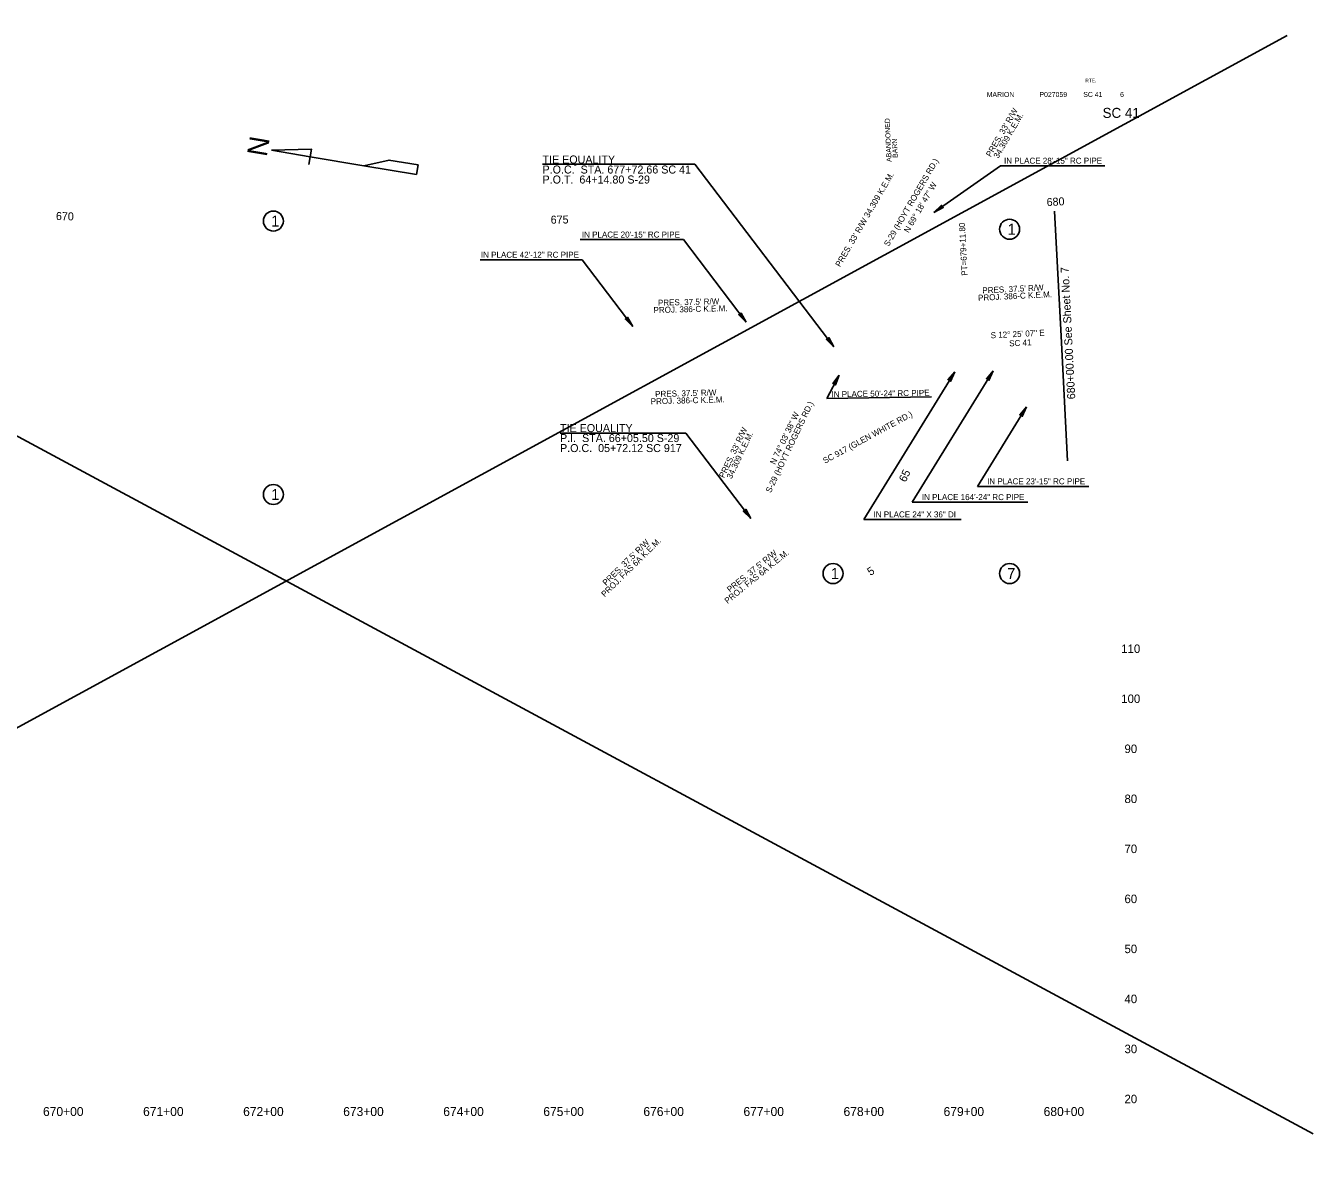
# Model space of a CAD drawing. Extents: x 2522404 to 2525275, y 885432 to 893540.
# Drawn here: x 2523877 to 2525164, y 886638 to 887766 of the extents above; entities that cross this region are included whole.
import ezdxf

# ---------------------------------------------------------------- set-up
doc = ezdxf.new("R2010")
doc.units = 0
for name, color, linetype in [('Default', 7, 'Continuous'), ('GN_Clip', 7, 'Continuous'), ('RD_DDB_ElevTX', 7, 'Continuous'), ('RD_DDB_Profile_EX', 7, 'Continuous'), ('RD_DDB_Profile_Lbl', 7, 'Continuous'), ('RD_EX_Misc', 7, 'Continuous'), ('RD_HC_Cl', 7, 'Continuous'), ('RD_HC_Data_Tic', 7, 'Continuous'), ('RD_HC_TX_Sta50', 7, 'Continuous'), ('RD_HY_TX1', 7, 'Continuous'), ('RD_PD_Final_LnLine', 7, 'Continuous'), ('RD_PD_RW_TX', 7, 'Continuous'), ('RD_SHT_IplotShp', 7, 'Continuous'), ('RD_SHT_MatchLine', 7, 'Continuous'), ('RD_Sketch8', 7, 'Continuous')]:
    doc.layers.add(name, color=color, linetype=linetype)

# ---------------------------------------------------------------- blocks, each defined once
blk = doc.blocks.new('ah_')
at = {"layer": 'Default'}
blk.add_lwpolyline([(0, 0), (-1.4, -10.4), (0, -8.8), (1.5, -10.4)], close=True, dxfattribs=at)
blk = doc.blocks.new('ah4')
at = {"layer": 'Default', "rotation": -90.00000000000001}
blk.add_blockref('ah_', (0, 0), dxfattribs=at)
blk = doc.blocks.new('AH4_')
at = {"layer": 'Default'}
blk.add_lwpolyline([(0, 0), (-10.4, 1.5), (-8.8, 0), (-10.4, -1.5)], close=True, dxfattribs=at)

msp = doc.modelspace()

# ---------------------------------------------------------------- linework, layer by layer
at = {"layer": 'RD_DDB_ElevTX'}
for p, q in [((2523107.1, 887765.8), (2525164, 886658.3)), ((2523086.7, 886637.9), (2525137.9, 887755.9))]:
    msp.add_line(p, q, dxfattribs=at)
at = {"layer": 'RD_EX_Misc'}
for centre in [(2524124.8, 887570.6), (2524860.6, 887562.4), (2524124.8, 887297.3), (2524684.1, 887218.3), (2524860.6, 887218.3)]:
    msp.add_circle(centre, 10, dxfattribs=at)
at = {"layer": 'RD_HY_TX1'}
for p, q in [((2524785, 887579.2), (2524851.4, 887625.8)), ((2524851.4, 887625.8), (2524955.9, 887625.8)), ((2524597.4, 887469.5), (2524534.6, 887552)), ((2524484, 887465.3), (2524433.4, 887531.9)), ((2524690.2, 887416.6), (2524677.8, 887393.3)), ((2524782.6, 887395), (2524677.8, 887393.3))]:
    msp.add_line(p, q, dxfattribs=at)
for points in [[(2524534.6, 887552), (2524431.5, 887552)], [(2524433.4, 887531.9), (2524331.5, 887531.9)], [(2524805.7, 887420), (2524714.8, 887272.3)], [(2524844.1, 887421), (2524763.2, 887289.6)], [(2524877.5, 887385), (2524828.4, 887305.4)], [(2524939.9, 887305.4), (2524828.4, 887305.4)], [(2524878.7, 887289.6), (2524763.2, 887289.6)], [(2524812.2, 887272.3), (2524714.9, 887272.3)]]:
    msp.add_lwpolyline(points, dxfattribs=at)
at = {"layer": 'RD_PD_RW_TX'}
for p, q in [((2524393.8, 887627.3), (2524546.1, 887627.3)), ((2524546.1, 887627.3), (2524684.9, 887444.9)), ((2524411.3, 887358.7), (2524536.9, 887358.7)), ((2524536.9, 887358.7), (2524601.9, 887273.3))]:
    msp.add_line(p, q, dxfattribs=at)
at = {"layer": 'RD_SHT_MatchLine'}
msp.add_lwpolyline([(2524918.4, 887330.8), (2524912, 887455.6), (2524905.6, 887580.5)], dxfattribs=at)
at = {"layer": 'RD_Sketch8'}
for p, q in [((2524163, 887642.6), (2524123, 887641.3)), ((2524123, 887641.3), (2524123, 887641.3)), ((2524123, 887641.3), (2524161.7, 887634.9)), ((2524161.7, 887634.9), (2524163, 887642.6)), ((2524163, 887642.6), (2524162.5, 887642.7)), ((2524160.4, 887627.1), (2524161.7, 887634.9)), ((2524215.3, 887625.9), (2524161.7, 887634.9)), ((2524240.6, 887631.6), (2524215.3, 887625.9)), ((2524215.3, 887625.9), (2524268, 887617.1)), ((2524269.6, 887626.7), (2524240.3, 887631.6)), ((2524240.3, 887631.6), (2524240.6, 887631.6)), ((2524268, 887617.1), (2524269.6, 887626.7))]:
    msp.add_line(p, q, dxfattribs=at)

# ---------------------------------------------------------------- block references
at = {"layer": 'RD_HY_TX1'}
for p, rotation in [((2524785, 887579.2), -145.18007028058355), ((2524484, 887465.3), -52.99465340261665), ((2524597.4, 887469.5), -52.99465340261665), ((2524690.2, 887416.6), 61.635532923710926)]:
    msp.add_blockref('ah4', p, dxfattribs=dict(at, rotation=rotation))
at = {"layer": 'RD_HY_TX1', "yscale": -0.9999999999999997, "rotation": 58.65092228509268}
for p in [(2524805.7, 887420), (2524844.1, 887421), (2524877.5, 887385)]:
    msp.add_blockref('ah4', p, dxfattribs=at)
at = {"layer": 'RD_PD_Final_LnLine'}
for p, rotation in [((2524684.9, 887444.9), -52.99465340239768), ((2524601.9, 887273.3), -52.9946534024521)]:
    msp.add_blockref('AH4_', p, dxfattribs=dict(at, rotation=rotation))

# ---------------------------------------------------------------- texts
at = {"layer": 'GN_Clip'}
for s, p in [('670+00', (2523894.6, 886676.1)), ('671+00', (2523994.6, 886676.1)), ('672+00', (2524094.6, 886676.1)), ('673+00', (2524194.6, 886676.1)), ('674+00', (2524294.6, 886676.1)), ('675+00', (2524394.6, 886676.1)), ('676+00', (2524494.6, 886676.1)), ('677+00', (2524594.6, 886676.1)), ('678+00', (2524694.6, 886676.1)), ('679+00', (2524794.6, 886676.1)), ('680+00', (2524894.6, 886676.1))]:
    msp.add_text(s, height=9, dxfattribs=at).set_placement(p)
at = {"layer": 'RD_DDB_Profile_EX'}
for s, rotation, p in [('680', 2.9168, (2524897.8, 887585.5)), ('670', 358.3577, (2523907.4, 887571.7)), ('675', 0.8578, (2524402, 887567.9)), ('65', 64.5588, (2524756.7, 887309)), ('5', 32.9169, (2524721.5, 887215.8))]:
    msp.add_text(s, height=8, rotation=rotation, dxfattribs=at).set_placement(p)
at = {"layer": 'RD_DDB_Profile_Lbl'}
for s, p in [('1', (2524122.6, 887565.1)), ('1', (2524858.5, 887556.9)), ('1', (2524122.6, 887291.8)), ('1', (2524681.9, 887212.8)), ('7', (2524858.1, 887212.8))]:
    msp.add_text(s, height=11, dxfattribs=at).set_placement(p)
at = {"layer": 'RD_EX_Misc'}
for s, height, p in [('RTE.', 3.5, (2524936.3, 887709.3)), ('MARION', 5, (2524837.7, 887694.6)), ('P027059', 5, (2524890.4, 887694.6)), ('SC 41', 5, (2524934.2, 887694.6)), ('6', 5, (2524971, 887694.6)), ('SC 41', 10, (2524953.5, 887673.7))]:
    msp.add_text(s, height=height, dxfattribs=at).set_placement(p)
at = {"layer": 'RD_HC_Cl'}
for s, height, rotation, p in [('TIE EQUALITY', 8, 360, (2524393.8, 887628.1)), ('P.O.C.  STA. 677+72.66 SC 41', 8, 360, (2524393.8, 887618.1)), ('S-29 (HOYT ROGERS RD.)', 6, 59.8115, (2524739.7, 887544.6)), ('P.O.T.  64+14.80 S-29', 8, 360, (2524393.8, 887608.1)), ('N 69%%d 18\' 47" W', 6, 59.8115, (2524759.7, 887558.3)), ('PT=679+11.80', 6, 92.9168, (2524818.6, 887516.1)), ('S 12%%d 25\' 07" E', 6, 2.848, (2524841.8, 887453.4)), ('SC 41 ', 6, 2.848, (2524860.3, 887445.3)), ('S-29 (HOYT ROGERS RD.)', 6, 64.5588, (2524621.9, 887298.4)), ('N 74%%d 03\' 38" W', 6, 64.5588, (2524626.2, 887326.7)), ('SC 917 (GLEN WHITE RD.)', 6, 28.4716, (2524676, 887327.9)), ('TIE EQUALITY', 8, 360, (2524411.3, 887359.7)), ('P.I.  STA. 66+05.50 S-29', 8, 360, (2524411.3, 887349.7)), ('P.O.C.  05+72.12 SC 917', 8, 360, (2524411.3, 887339.7))]:
    msp.add_text(s, height=height, rotation=rotation, dxfattribs=at).set_placement(p)
at = {"layer": 'RD_HC_Data_Tic'}
for s, p in [('ABANDONED', (2524742.7, 887629.8)), ('  BARN', (2524749, 887630))]:
    msp.add_text(s, height=5, rotation=92.6257, dxfattribs=at).set_placement(p)
at = {"layer": 'RD_HC_TX_Sta50'}
for s, p in [('110', (2524972.2, 887138.9)), ('100', (2524972.2, 887088.9)), ('90', (2524975.4, 887038.9)), ('80', (2524975.4, 886988.9)), ('70', (2524975.4, 886938.9)), ('60', (2524975.4, 886888.9)), ('50', (2524975.4, 886838.9)), ('40', (2524975.4, 886788.9)), ('30', (2524975.4, 886738.9)), ('20', (2524975.4, 886688.9))]:
    msp.add_text(s, height=8.5, dxfattribs=at).set_placement(p)
at = {"layer": 'RD_HY_TX1'}
for s, p in [('IN PLACE 28\'-15" RC PIPE', (2524855, 887627.9)), ('IN PLACE 20\'-15" RC PIPE', (2524433.1, 887554.1)), ('IN PLACE 42\'-12" RC PIPE', (2524332.2, 887533.9)), ('IN PLACE 23\'-15" RC PIPE', (2524838.1, 887307.5)), ('IN PLACE 164\'-24" RC PIPE', (2524772.9, 887291.7)), ('IN PLACE 24" X 36" DI', (2524724.6, 887274.4))]:
    msp.add_text(s, height=6, dxfattribs=at).set_placement(p)
msp.add_text('IN PLACE 50\'-24" RC PIPE', height=6, rotation=0.9556, dxfattribs=at).set_placement((2524682.6, 887394.4))
at = {"layer": 'RD_SHT_IplotShp'}
for s, rotation, p in [("PRES. 33' R/W", 59.8115, (2524841.7, 887634.1)), ('34.309 K.E.M.', 59.8115, (2524849.2, 887632.6)), ("PRES. 33' R/W 34.309 K.E.M.", 59.8115, (2524691.2, 887524.2)), ("PRES. 37.5' R/W", 2.9168, (2524833.5, 887498.2)), ("PRES. 37.5' R/W", 1.5081, (2524509.2, 887485.9)), ('PROJ. 386-C K.E.M.', 2.9168, (2524829.2, 887490.8)), ('PROJ. 386-C K.E.M.', 1.5081, (2524504.8, 887478.6)), ('PROJ. 386-C K.E.M.', 1.5081, (2524502, 887387.4)), ("PRES. 37.5' R/W", 1.5081, (2524506.4, 887394.7)), ("PRES. 33' R/W ", 64.5588, (2524575.2, 887313.3)), ('34.309 K.E.M.', 64.5588, (2524582.8, 887312.4)), ('PROJ. FAS 6A K.E.M.', 44.5971, (2524456, 887194.4)), ("PRES. 37.5' R/W", 44.5971, (2524457.3, 887205.8)), ('PROJ. FAS 6A K.E.M.', 39.0798, (2524578.7, 887187.8)), ("PRES. 37.5' R/W", 39.0798, (2524581.1, 887199.1))]:
    msp.add_text(s, height=6, rotation=rotation, dxfattribs=at).set_placement(p)
at = {"layer": 'RD_SHT_MatchLine'}
msp.add_text(' 680+00.00 See Sheet No. 7', height=8, rotation=92.9168, dxfattribs=at).set_placement((2524926.4, 887389.7))
at = {"layer": 'RD_Sketch8'}
msp.add_text('N', height=20, rotation=80.4983, dxfattribs=at).set_placement((2524118.1, 887634.2))

doc.saveas('drawing.dxf')
